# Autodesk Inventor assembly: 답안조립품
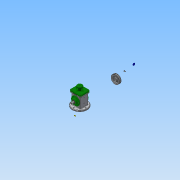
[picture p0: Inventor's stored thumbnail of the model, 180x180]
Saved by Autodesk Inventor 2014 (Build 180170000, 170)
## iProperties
Created: 2018-10
Part Number: 답안조립품
Document SubType Name: Assembly
Designer: Administrator
Author: Administrator
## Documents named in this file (18)
- C:\Users\Administrator\Desktop\481007V1008\답안조립품.iam
- C:\Users\Administrator\Desktop\481007V1008\본체.ipt
- C:\Users\Administrator\Desktop\481007V1008\E-링.ipt
- C:\Users\Administrator\Desktop\481007V1008\V-벨트풀리.ipt
- C:\Users\Administrator\Desktop\481007V1008\덮개.ipt
- C:\Users\Administrator\Desktop\481007V1008\뒤커버.ipt
- C:\Users\Administrator\Desktop\481007V1008\링크.ipt
- C:\Users\Administrator\Desktop\481007V1008\베어링 17 x 40 x 12.ipt
- C:\Users\Administrator\Desktop\481007V1008\볼트 M4 x 8.ipt
- C:\Users\Administrator\Desktop\481007V1008\볼트 M4 x 10.ipt
- C:\Users\Administrator\Desktop\481007V1008\슬라이더.ipt
- C:\Users\Administrator\Desktop\481007V1008\앞커버.ipt
- C:\Users\Administrator\Desktop\481007V1008\오일 실 17 30 8.ipt
- C:\Users\Administrator\Desktop\481007V1008\와셔 4x16.ipt
- C:\Users\Administrator\Desktop\481007V1008\클레비스 핀 6 x 22.ipt
- 클레비스 핀 6 x 22.ipt
- C:\Users\Administrator\Desktop\481007V1008\키 4 x 4 x 12.ipt
- C:\Users\Administrator\Desktop\481007V1008\편심축.ipt
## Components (2 placed, 2 different names)
1. E-링:1 — 각도:1
2. V-벨트풀리:1
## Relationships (1: Angle 1)
- 각도:1 [Angle]: E-링:1
